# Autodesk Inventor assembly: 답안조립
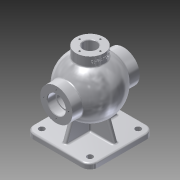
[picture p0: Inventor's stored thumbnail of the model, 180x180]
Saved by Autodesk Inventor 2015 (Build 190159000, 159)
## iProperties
Created: 2025-08
Part Number: 답안조립
Document SubType Name: Assembly
Designer: USER
Author: USER
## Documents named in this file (2)
- C:\Users\USER\Downloads\750808V1009\답안조립.iam
- C:\Users\USER\Downloads\750808V1009\본체.ipt
